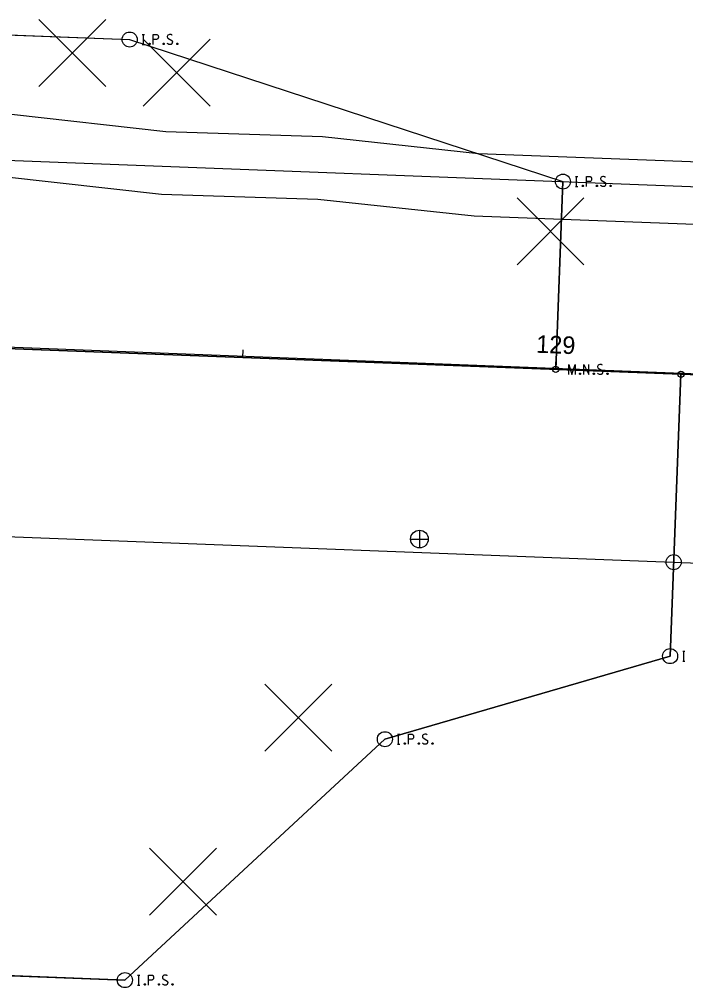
# Model space of a CAD drawing. Extents: x 2003596 to 2006933, y 570827 to 573780.
# Drawn here: x 2005548.5 to 2005654.9, y 572513.6 to 572668.1 of the extents above; entities that cross this region are included whole.
import ezdxf

# ---------------------------------------------------------------- set-up
doc = ezdxf.new("R2010")
doc.units = 0
for name, color, linetype in [('DT_X_Contour_Major', 7, 'Continuous'), ('DT_X_Spot_Elev', 7, 'Continuous'), ('DT_X_TIN_Hull', 7, 'Continuous'), ('GE_X_Alignment', 7, 'Continuous'), ('GE_X_Alignment_100_Stations', 7, 'Continuous'), ('GE_X_Alignment_500_Stations', 7, 'Continuous'), ('RW_X_CL', 7, 'Continuous'), ('RW_X_Esmt_SH', 7, 'Continuous'), ('SC_Scratch10', 7, 'Continuous'), ('SV_P_Mon_Cells_Set', 7, 'Continuous'), ('SV_X_Control_Cells_Found', 7, 'Continuous'), ('UT_X_Overhead_Electric', 7, 'Continuous'), ('UT_X_Overhead_Telecom', 7, 'Continuous'), ('UT_X_Telecom', 7, 'Continuous')]:
    doc.layers.add(name, color=color, linetype=linetype)

msp = doc.modelspace()

# ---------------------------------------------------------------- linework, layer by layer
at = {"layer": 'DT_X_Contour_Major'}
for points in [[(2005636.2, 572611.4), (2005636.2, 572613), (2005636.7, 572611.4), (2005637.19, 572613), (2005637.19, 572611.4)], [(2005638.57, 572611.4), (2005638.57, 572613), (2005639.39, 572611.4), (2005639.39, 572613)], [(2005641.54, 572612.88), (2005641.52, 572612.91), (2005641.49, 572612.93), (2005641.39, 572612.97), (2005641.27, 572613), (2005641.18, 572613), (2005641.15, 572613), (2005641, 572612.96), (2005640.88, 572612.88), (2005640.81, 572612.78), (2005640.78, 572612.68), (2005640.78, 572612.61), (2005640.81, 572612.5), (2005640.89, 572612.42), (2005641.5, 572612.04), (2005641.55, 572611.99), (2005641.58, 572611.94), (2005641.6, 572611.86), (2005641.6, 572611.79), (2005641.59, 572611.71), (2005641.58, 572611.66), (2005641.55, 572611.6), (2005641.53, 572611.55), (2005641.51, 572611.51), (2005641.48, 572611.47), (2005641.44, 572611.45), (2005641.4, 572611.42), (2005641.37, 572611.41), (2005641.27, 572611.4), (2005641.11, 572611.4), (2005641.01, 572611.42), (2005640.87, 572611.51), (2005640.78, 572611.58)], [(2005637.96, 572611.61), (2005638.02, 572611.61), (2005638.05, 572611.58), (2005638.08, 572611.53), (2005638.08, 572611.47), (2005638.05, 572611.42), (2005638.02, 572611.4), (2005637.96, 572611.4), (2005637.93, 572611.42), (2005637.9, 572611.47), (2005637.9, 572611.53), (2005637.93, 572611.58), (2005637.96, 572611.61)], [(2005640.18, 572611.61), (2005640.23, 572611.61), (2005640.27, 572611.58), (2005640.3, 572611.53), (2005640.3, 572611.47), (2005640.27, 572611.42), (2005640.23, 572611.4), (2005640.18, 572611.4), (2005640.14, 572611.42), (2005640.11, 572611.47), (2005640.11, 572611.53), (2005640.14, 572611.58), (2005640.18, 572611.61)], [(2005642.36, 572611.61), (2005642.41, 572611.61), (2005642.45, 572611.58), (2005642.48, 572611.53), (2005642.48, 572611.47), (2005642.45, 572611.42), (2005642.41, 572611.4), (2005642.36, 572611.4), (2005642.33, 572611.42), (2005642.29, 572611.47), (2005642.29, 572611.53), (2005642.33, 572611.58), (2005642.36, 572611.61)]]:
    msp.add_lwpolyline(points, dxfattribs=at)
for centre in [(2005634.11, 572612.2), (2005654.09, 572611.43)]:
    msp.add_circle(centre, 0.497, dxfattribs=at)
at = {"layer": 'DT_X_Spot_Elev'}
for p, q in [((2005486.13, 572667.91), (2005566.08, 572664.84)), ((2005566.08, 572664.84), (2005635.26, 572642.17)), ((2005635.26, 572642.17), (2005634.11, 572612.2)), ((2005634.11, 572612.2), (2005465.42, 572618.67)), ((2005465.42, 572618.67), (2005654.09, 572611.43)), ((2005654.09, 572611.43), (2005634.11, 572612.2)), ((2005654.09, 572611.43), (2005652.37, 572566.46)), ((2006023.62, 572597.25), (2005654.09, 572611.43)), ((2005652.37, 572566.46), (2005606.83, 572553.2)), ((2005606.83, 572553.2), (2005565.32, 572514.76)), ((2005565.32, 572514.76), (2005490.38, 572517.64))]:
    msp.add_line(p, q, dxfattribs=at)
at = {"layer": 'DT_X_TIN_Hull'}
for p, q in [((2005551.57, 572668.06), (2005562.26, 572657.36)), ((2005562.26, 572668.06), (2005551.57, 572657.36)), ((2005568.25, 572664.88), (2005578.95, 572654.19)), ((2005578.95, 572664.88), (2005568.25, 572654.19)), ((2005556.92, 572662.71), (2005556.92, 572662.71)), ((2005573.6, 572659.54), (2005573.6, 572659.54)), ((2005627.93, 572639.57), (2005638.62, 572628.87)), ((2005638.62, 572639.57), (2005627.93, 572628.87)), ((2005633.27, 572634.22), (2005633.27, 572634.22)), ((2005587.66, 572561.97), (2005598.35, 572551.28)), ((2005598.35, 572561.97), (2005587.66, 572551.28)), ((2005593, 572556.62), (2005593, 572556.62)), ((2005569.24, 572535.84), (2005579.93, 572525.14)), ((2005579.93, 572535.84), (2005569.24, 572525.14)), ((2005574.58, 572530.49), (2005574.58, 572530.49))]:
    msp.add_line(p, q, dxfattribs=at)
at = {"layer": 'GE_X_Alignment'}
msp.add_line((2005031.48, 572635.32), (2006023.62, 572597.25), dxfattribs=at)
at = {"layer": 'GE_X_Alignment_100_Stations'}
for p, q in [((2005584.14, 572614.11), (2005584.19, 572615.31)), ((2005634.11, 572612.2), (2005634.18, 572614.19))]:
    msp.add_line(p, q, dxfattribs=at)
at = {"layer": 'GE_X_Alignment_500_Stations'}
msp.add_line((2005634.11, 572612.2), (2005634.15, 572613.4), dxfattribs=at)
at = {"layer": 'RW_X_CL'}
msp.add_line((2006023.62, 572597.25), (2005031.48, 572635.32), dxfattribs=at)
at = {"layer": 'RW_X_Esmt_SH'}
for p, q in [((2005034.78, 572665.22), (2006024.45, 572627.24)), ((2005634.11, 572612.2), (2005635.26, 572642.17)), ((2005652.37, 572566.46), (2005654.09, 572611.43)), ((2005028.18, 572605.42), (2006022.8, 572567.26))]:
    msp.add_line(p, q, dxfattribs=at)
at = {"layer": 'SC_Scratch10'}
msp.add_line((2006023.71, 572597.25), (2005465.42, 572618.88), dxfattribs=at)
at = {"layer": 'SV_P_Mon_Cells_Set'}
for points in [[(2005568.09, 572665.65), (2005568.45, 572665.65)], [(2005568.27, 572664.05), (2005568.27, 572665.65)], [(2005569.23, 572664.26), (2005569.29, 572664.26), (2005569.32, 572664.23), (2005569.35, 572664.18), (2005569.35, 572664.12), (2005569.32, 572664.07), (2005569.29, 572664.05), (2005569.23, 572664.05), (2005569.2, 572664.07), (2005569.16, 572664.12), (2005569.16, 572664.18), (2005569.2, 572664.23), (2005569.23, 572664.26)], [(2005569.84, 572664.05), (2005569.84, 572665.65), (2005570.37, 572665.65), (2005570.42, 572665.63), (2005570.5, 572665.61), (2005570.53, 572665.58), (2005570.56, 572665.56), (2005570.61, 572665.49), (2005570.64, 572665.43), (2005570.66, 572665.33), (2005570.66, 572665.18), (2005570.65, 572665.13), (2005570.63, 572665.05), (2005570.59, 572664.96), (2005570.54, 572664.93), (2005570.51, 572664.9), (2005570.45, 572664.88), (2005570.37, 572664.86), (2005569.84, 572664.86)], [(2005571.48, 572664.26), (2005571.53, 572664.26), (2005571.57, 572664.23), (2005571.6, 572664.18), (2005571.6, 572664.12), (2005571.57, 572664.07), (2005571.53, 572664.05), (2005571.48, 572664.05), (2005571.45, 572664.07), (2005571.41, 572664.12), (2005571.41, 572664.18), (2005571.45, 572664.23), (2005571.48, 572664.26)], [(2005572.85, 572665.53), (2005572.82, 572665.56), (2005572.79, 572665.58), (2005572.69, 572665.62), (2005572.57, 572665.65), (2005572.48, 572665.65), (2005572.45, 572665.65), (2005572.31, 572665.61), (2005572.18, 572665.53), (2005572.11, 572665.43), (2005572.09, 572665.33), (2005572.09, 572665.25), (2005572.11, 572665.15), (2005572.2, 572665.07), (2005572.8, 572664.69), (2005572.86, 572664.64), (2005572.88, 572664.59), (2005572.9, 572664.51), (2005572.9, 572664.44), (2005572.89, 572664.36), (2005572.88, 572664.31), (2005572.86, 572664.25), (2005572.83, 572664.2), (2005572.81, 572664.16), (2005572.78, 572664.12), (2005572.75, 572664.1), (2005572.7, 572664.07), (2005572.67, 572664.06), (2005572.57, 572664.05), (2005572.42, 572664.05), (2005572.32, 572664.07), (2005572.17, 572664.16), (2005572.09, 572664.23)], [(2005573.66, 572664.26), (2005573.72, 572664.26), (2005573.75, 572664.23), (2005573.78, 572664.18), (2005573.78, 572664.12), (2005573.75, 572664.07), (2005573.72, 572664.05), (2005573.66, 572664.05), (2005573.63, 572664.07), (2005573.6, 572664.12), (2005573.6, 572664.18), (2005573.63, 572664.23), (2005573.66, 572664.26)], [(2005568.09, 572664.05), (2005568.45, 572664.05)], [(2005637.28, 572642.98), (2005637.63, 572642.98)], [(2005637.45, 572641.38), (2005637.45, 572642.98)], [(2005639.02, 572641.38), (2005639.02, 572642.98), (2005639.55, 572642.98), (2005639.6, 572642.96), (2005639.68, 572642.94), (2005639.71, 572642.91), (2005639.75, 572642.89), (2005639.79, 572642.82), (2005639.82, 572642.76), (2005639.84, 572642.66), (2005639.84, 572642.51), (2005639.83, 572642.46), (2005639.81, 572642.38), (2005639.77, 572642.3), (2005639.72, 572642.26), (2005639.69, 572642.23), (2005639.64, 572642.21), (2005639.55, 572642.19), (2005639.02, 572642.19)], [(2005642.03, 572642.86), (2005642.01, 572642.89), (2005641.97, 572642.91), (2005641.87, 572642.95), (2005641.75, 572642.98), (2005641.66, 572642.98), (2005641.63, 572642.98), (2005641.49, 572642.94), (2005641.37, 572642.86), (2005641.29, 572642.76), (2005641.27, 572642.66), (2005641.27, 572642.59), (2005641.29, 572642.48), (2005641.38, 572642.4), (2005641.98, 572642.02), (2005642.04, 572641.97), (2005642.06, 572641.92), (2005642.08, 572641.84), (2005642.08, 572641.77), (2005642.07, 572641.69), (2005642.06, 572641.64), (2005642.04, 572641.58), (2005642.02, 572641.53), (2005641.99, 572641.49), (2005641.96, 572641.45), (2005641.93, 572641.43), (2005641.88, 572641.4), (2005641.85, 572641.39), (2005641.75, 572641.38), (2005641.6, 572641.38), (2005641.5, 572641.4), (2005641.36, 572641.49), (2005641.27, 572641.57)], [(2005637.28, 572641.38), (2005637.63, 572641.38)], [(2005638.41, 572641.59), (2005638.47, 572641.59), (2005638.5, 572641.57), (2005638.53, 572641.51), (2005638.53, 572641.45), (2005638.5, 572641.4), (2005638.47, 572641.38), (2005638.41, 572641.38), (2005638.38, 572641.4), (2005638.35, 572641.45), (2005638.35, 572641.51), (2005638.38, 572641.57), (2005638.41, 572641.59)], [(2005640.66, 572641.59), (2005640.72, 572641.59), (2005640.75, 572641.57), (2005640.78, 572641.51), (2005640.78, 572641.45), (2005640.75, 572641.4), (2005640.72, 572641.38), (2005640.66, 572641.38), (2005640.63, 572641.4), (2005640.59, 572641.45), (2005640.59, 572641.51), (2005640.63, 572641.57), (2005640.66, 572641.59)], [(2005642.84, 572641.59), (2005642.9, 572641.59), (2005642.93, 572641.57), (2005642.96, 572641.51), (2005642.96, 572641.45), (2005642.93, 572641.4), (2005642.9, 572641.38), (2005642.84, 572641.38), (2005642.81, 572641.4), (2005642.78, 572641.45), (2005642.78, 572641.51), (2005642.81, 572641.57), (2005642.84, 572641.59)], [(2005654.39, 572567.26), (2005654.74, 572567.26)], [(2005654.56, 572565.66), (2005654.56, 572567.26)], [(2005654.39, 572565.66), (2005654.74, 572565.66)], [(2005608.84, 572554), (2005609.2, 572554)], [(2005609.02, 572552.4), (2005609.02, 572554)], [(2005610.59, 572552.4), (2005610.59, 572554), (2005611.11, 572554), (2005611.17, 572553.99), (2005611.25, 572553.96), (2005611.28, 572553.94), (2005611.31, 572553.91), (2005611.36, 572553.85), (2005611.39, 572553.79), (2005611.41, 572553.69), (2005611.41, 572553.53), (2005611.4, 572553.48), (2005611.38, 572553.41), (2005611.34, 572553.32), (2005611.29, 572553.28), (2005611.26, 572553.26), (2005611.2, 572553.23), (2005611.11, 572553.22), (2005610.59, 572553.22)], [(2005613.6, 572553.89), (2005613.57, 572553.91), (2005613.54, 572553.94), (2005613.44, 572553.98), (2005613.32, 572554), (2005613.23, 572554), (2005613.2, 572554), (2005613.05, 572553.96), (2005612.93, 572553.89), (2005612.86, 572553.79), (2005612.83, 572553.69), (2005612.83, 572553.61), (2005612.86, 572553.51), (2005612.94, 572553.42), (2005613.55, 572553.04), (2005613.61, 572552.99), (2005613.63, 572552.94), (2005613.65, 572552.87), (2005613.65, 572552.79), (2005613.64, 572552.72), (2005613.63, 572552.67), (2005613.61, 572552.6), (2005613.58, 572552.55), (2005613.56, 572552.51), (2005613.53, 572552.48), (2005613.5, 572552.45), (2005613.45, 572552.43), (2005613.42, 572552.41), (2005613.32, 572552.4), (2005613.17, 572552.4), (2005613.07, 572552.43), (2005612.92, 572552.51), (2005612.83, 572552.59)], [(2005608.84, 572552.4), (2005609.2, 572552.4)], [(2005609.98, 572552.61), (2005610.03, 572552.61), (2005610.07, 572552.59), (2005610.1, 572552.54), (2005610.1, 572552.48), (2005610.07, 572552.43), (2005610.03, 572552.4), (2005609.98, 572552.4), (2005609.95, 572552.43), (2005609.91, 572552.48), (2005609.91, 572552.54), (2005609.95, 572552.59), (2005609.98, 572552.61)], [(2005612.23, 572552.61), (2005612.28, 572552.61), (2005612.32, 572552.59), (2005612.35, 572552.54), (2005612.35, 572552.48), (2005612.32, 572552.43), (2005612.28, 572552.4), (2005612.23, 572552.4), (2005612.2, 572552.43), (2005612.16, 572552.48), (2005612.16, 572552.54), (2005612.2, 572552.59), (2005612.23, 572552.61)], [(2005614.41, 572552.61), (2005614.47, 572552.61), (2005614.5, 572552.59), (2005614.53, 572552.54), (2005614.53, 572552.48), (2005614.5, 572552.43), (2005614.47, 572552.4), (2005614.41, 572552.4), (2005614.38, 572552.43), (2005614.34, 572552.48), (2005614.34, 572552.54), (2005614.38, 572552.59), (2005614.41, 572552.61)], [(2005567.34, 572515.56), (2005567.69, 572515.56)], [(2005567.52, 572513.96), (2005567.52, 572515.56)], [(2005569.08, 572513.96), (2005569.08, 572515.56), (2005569.61, 572515.56), (2005569.67, 572515.55), (2005569.74, 572515.53), (2005569.78, 572515.5), (2005569.81, 572515.48), (2005569.85, 572515.41), (2005569.89, 572515.35), (2005569.91, 572515.25), (2005569.91, 572515.1), (2005569.9, 572515.05), (2005569.88, 572514.97), (2005569.83, 572514.88), (2005569.79, 572514.85), (2005569.75, 572514.82), (2005569.7, 572514.8), (2005569.61, 572514.78), (2005569.08, 572514.78)], [(2005572.09, 572515.45), (2005572.07, 572515.48), (2005572.04, 572515.5), (2005571.94, 572515.54), (2005571.82, 572515.56), (2005571.73, 572515.56), (2005571.69, 572515.56), (2005571.55, 572515.53), (2005571.43, 572515.45), (2005571.35, 572515.35), (2005571.33, 572515.25), (2005571.33, 572515.17), (2005571.35, 572515.07), (2005571.44, 572514.98), (2005572.05, 572514.61), (2005572.1, 572514.56), (2005572.12, 572514.51), (2005572.15, 572514.43), (2005572.15, 572514.35), (2005572.13, 572514.28), (2005572.12, 572514.23), (2005572.1, 572514.17), (2005572.08, 572514.11), (2005572.06, 572514.08), (2005572.02, 572514.04), (2005571.99, 572514.01), (2005571.95, 572513.99), (2005571.91, 572513.98), (2005571.82, 572513.96), (2005571.66, 572513.96), (2005571.56, 572513.99), (2005571.42, 572514.08), (2005571.33, 572514.15)], [(2005567.34, 572513.96), (2005567.69, 572513.96)], [(2005568.48, 572514.18), (2005568.53, 572514.18), (2005568.56, 572514.15), (2005568.6, 572514.1), (2005568.6, 572514.04), (2005568.56, 572513.99), (2005568.53, 572513.96), (2005568.48, 572513.96), (2005568.44, 572513.99), (2005568.41, 572514.04), (2005568.41, 572514.1), (2005568.44, 572514.15), (2005568.48, 572514.18)], [(2005570.72, 572514.18), (2005570.78, 572514.18), (2005570.81, 572514.15), (2005570.85, 572514.1), (2005570.85, 572514.04), (2005570.81, 572513.99), (2005570.78, 572513.96), (2005570.72, 572513.96), (2005570.69, 572513.99), (2005570.66, 572514.04), (2005570.66, 572514.1), (2005570.69, 572514.15), (2005570.72, 572514.18)], [(2005572.91, 572514.18), (2005572.96, 572514.18), (2005572.99, 572514.15), (2005573.03, 572514.1), (2005573.03, 572514.04), (2005572.99, 572513.99), (2005572.96, 572513.96), (2005572.91, 572513.96), (2005572.87, 572513.99), (2005572.84, 572514.04), (2005572.84, 572514.1), (2005572.87, 572514.15), (2005572.91, 572514.18)]]:
    msp.add_lwpolyline(points, dxfattribs=at)
for centre in [(2005566.08, 572664.84), (2005635.26, 572642.17), (2005652.94, 572581.45), (2005652.37, 572566.46), (2005606.83, 572553.2), (2005565.32, 572514.76)]:
    msp.add_circle(centre, 1.2, dxfattribs=at)
at = {"layer": 'SV_X_Control_Cells_Found'}
for p, q in [((2005612.35, 572586.55), (2005612.35, 572583.73)), ((2005610.94, 572585.14), (2005613.76, 572585.14))]:
    msp.add_line(p, q, dxfattribs=at)
msp.add_circle((2005612.35, 572585.14), 1.41, dxfattribs=at)
at = {"layer": 'UT_X_Overhead_Electric'}
msp.add_line((2005652.37, 572566.46), (2005652.94, 572581.45), dxfattribs=at)
for points in [[(2005410.42, 572650.8), (2005464.45, 572663.01), (2005486.13, 572667.91), (2005566.08, 572664.84), (2005635.26, 572642.17)], [(2005408.12, 572590.85), (2005466.41, 572573.6), (2005490.38, 572517.64), (2005565.32, 572514.76), (2005606.83, 572553.2), (2005652.37, 572566.46)]]:
    msp.add_lwpolyline(points, dxfattribs=at)
at = {"layer": 'UT_X_Overhead_Telecom'}
msp.add_lwpolyline([(2005410.42, 572650.8), (2005464.45, 572663.01), (2005486.13, 572667.91), (2005566.08, 572664.84), (2005635.26, 572642.17)], dxfattribs=at)
at = {"layer": 'UT_X_Telecom'}
for points in [[(2005147.76, 572660.26), (2005421.1, 572658.32), (2005446.17, 572659.8), (2005471.38, 572659.28), (2005497.09, 572658.54), (2005522.25, 572656.73), (2005547.24, 572652.92), (2005571.87, 572650.16), (2005596.85, 572649.37), (2005621.79, 572646.67), (2006021.03, 572631.61)], [(2005147.98, 572650.26), (2005421.36, 572648.31), (2005446.36, 572649.8), (2005471.14, 572649.29), (2005496.59, 572648.55), (2005521.14, 572646.78), (2005545.93, 572643), (2005571.15, 572640.18), (2005596.15, 572639.39), (2005621.06, 572636.69), (2006021.19, 572621.6)]]:
    msp.add_lwpolyline(points, dxfattribs=at)

# ---------------------------------------------------------------- texts
at = {"layer": 'GE_X_Alignment_100_Stations'}
msp.add_text('129', height=2.8, rotation=357.8026, dxfattribs=at).set_placement((2005630.95, 572614.87))

doc.saveas('drawing.dxf')
